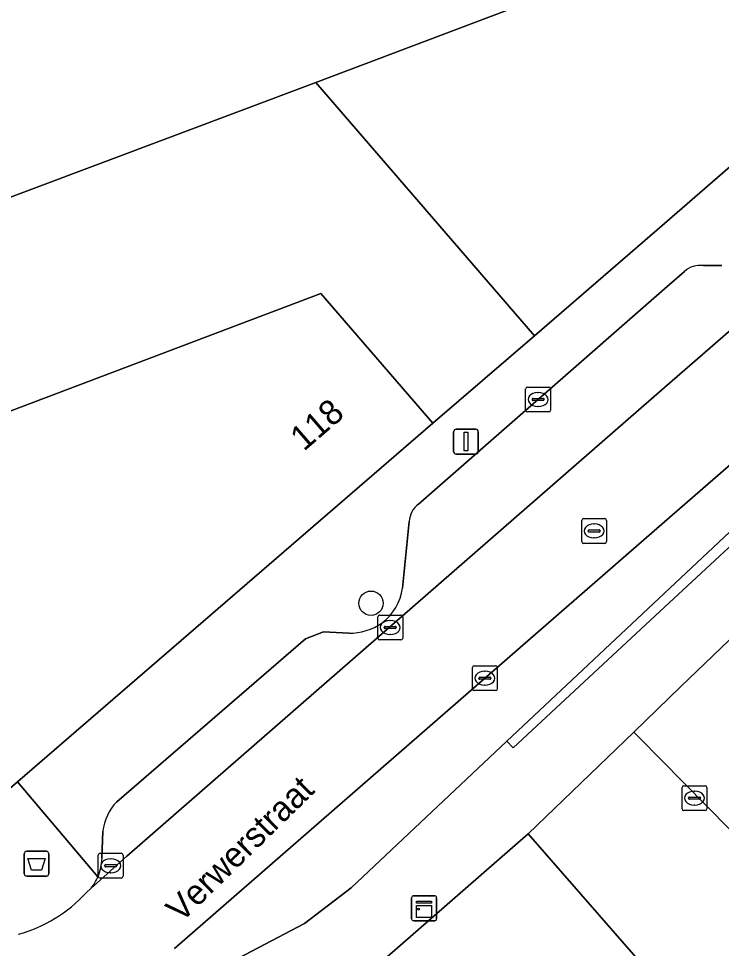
# Model space of a CAD drawing. Extents: x 160856 to 161310, y 384024 to 384878.
# Drawn here: x 160974.04 to 161002.28, y 384577.71 to 384615.1 of the extents above; entities that cross this region are included whole.
import ezdxf

# ---------------------------------------------------------------- set-up
doc = ezdxf.new("R2010")
doc.units = 0
for name, color, linetype in [('IMGEO_Afvalbak', 7, 'Continuous'), ('IMGEO_Boom', 7, 'Continuous'), ('IMGEO_Kast', 7, 'Continuous'), ('IMGEO_Kolk', 7, 'Continuous'), ('IMGEO_Lichtmast', 7, 'Continuous'), ('IMGEO_Openbare_ruimte_label', 7, 'Continuous'), ('IMGEO_Pand', 7, 'Continuous'), ('IMGEO_Pand_nummerreeks', 7, 'Continuous'), ('IMGEO_Parkeervlak_open', 7, 'Continuous'), ('IMGEO_Rijbaan_lokaal_gesloten', 7, 'Continuous'), ('IMGEO_Rijbaan_lokaal_open', 7, 'Continuous'), ('IMGEO_Rioolput', 7, 'Continuous'), ('IMGEO_Voetpad_open', 7, 'Continuous')]:
    doc.layers.add(name, color=color, linetype=linetype)

msp = doc.modelspace()

# ---------------------------------------------------------------- linework, layer by layer
at = {"layer": 'IMGEO_Afvalbak'}
for p, q in [((160974.362, 384581.619), (160975.152, 384581.619)), ((160975.152, 384581.619), (160974.362, 384581.619)), ((160974.262, 384580.719), (160974.262, 384581.519)), ((160974.262, 384581.519), (160974.262, 384580.719)), ((160975.252, 384581.519), (160975.252, 384580.719)), ((160975.252, 384580.719), (160975.252, 384581.519)), ((160975.152, 384580.619), (160974.362, 384580.619)), ((160974.362, 384580.619), (160975.152, 384580.619))]:
    msp.add_line(p, q, dxfattribs=at)
msp.add_lwpolyline([(160974.405, 384581.333), (160975.109, 384581.333), (160974.96, 384580.863), (160974.554, 384580.863), (160974.405, 384581.333)], dxfattribs=at)
for centre, start, end in [((160974.362, 384581.519), 90, 180), ((160974.362, 384581.519), 90, 180), ((160975.152, 384581.519), 0, 90), ((160975.152, 384581.519), 360, 90), ((160974.362, 384580.719), 180, 270), ((160974.362, 384580.719), 180, 270), ((160975.152, 384580.719), 270, 0), ((160975.152, 384580.719), 270, 0)]:
    msp.add_arc(centre, 0.1, start, end, dxfattribs=at)
at = {"layer": 'IMGEO_Boom'}
msp.add_circle((160988.2, 384591.593), 0.489, dxfattribs=at)
at = {"layer": 'IMGEO_Kast'}
for p, q in [((160989.833, 384578.904), (160989.833, 384579.745)), ((160989.833, 384579.745), (160989.833, 384578.904)), ((160989.908, 384579.829), (160990.749, 384579.829)), ((160990.749, 384579.829), (160989.908, 384579.829)), ((160990.833, 384579.754), (160990.833, 384578.913)), ((160990.833, 384578.913), (160990.833, 384579.754)), ((160990.758, 384578.829), (160989.917, 384578.829)), ((160989.917, 384578.829), (160990.758, 384578.829))]:
    msp.add_line(p, q, dxfattribs=at)
for points in [[(160990.028, 384579.619), (160990.628, 384579.619), (160990.628, 384579.534), (160990.028, 384579.534), (160990.028, 384579.619)], [(160990.028, 384579.444), (160990.628, 384579.444), (160990.628, 384578.955), (160990.028, 384578.955), (160990.028, 384579.444)]]:
    msp.add_lwpolyline(points, dxfattribs=at)
msp.add_circle((160990.112, 384579.293), 0.0377, dxfattribs=at)
for centre, start, end in [((160989.911, 384579.751), 92.4484, 184.2845), ((160989.911, 384579.751), 92.4484, 184.2845), ((160990.755, 384579.751), 2.4484, 94.2845), ((160990.755, 384579.751), 2.4484, 94.2845), ((160989.911, 384578.907), 182.4484, 274.2845), ((160989.911, 384578.907), 182.4484, 274.2845), ((160990.755, 384578.907), 272.4484, 4.2845), ((160990.755, 384578.907), 272.4484, 4.2845)]:
    msp.add_arc(centre, 0.0779, start, end, dxfattribs=at)
at = {"layer": 'IMGEO_Kolk'}
for p, q in [((160994.49, 384600.285), (160995.342, 384600.285)), ((160994.415, 384599.359), (160994.415, 384600.211)), ((160994.903, 384600.065), (160994.928, 384600.065)), ((160995.416, 384600.211), (160995.416, 384599.359)), ((160994.674, 384599.779), (160994.674, 384599.791)), ((160995.112, 384599.742), (160994.714, 384599.742)), ((160994.717, 384599.828), (160995.115, 384599.828)), ((160994.926, 384599.505), (160994.901, 384599.505)), ((160995.158, 384599.791), (160995.158, 384599.779)), ((160995.342, 384599.285), (160994.49, 384599.285)), ((160988.472, 384590.192), (160988.472, 384591.044)), ((160988.547, 384591.118), (160989.399, 384591.118)), ((160988.96, 384590.898), (160988.985, 384590.898)), ((160989.473, 384591.044), (160989.473, 384590.192)), ((160988.731, 384590.612), (160988.731, 384590.624)), ((160989.169, 384590.575), (160988.771, 384590.575)), ((160988.774, 384590.661), (160989.172, 384590.661)), ((160989.215, 384590.624), (160989.215, 384590.612)), ((160988.983, 384590.338), (160988.958, 384590.338)), ((160989.399, 384590.118), (160988.547, 384590.118)), ((160992.35, 384589.079), (160993.202, 384589.079)), ((160992.275, 384588.153), (160992.275, 384589.005)), ((160992.763, 384588.859), (160992.788, 384588.859)), ((160993.276, 384589.005), (160993.276, 384588.153)), ((160992.534, 384588.573), (160992.534, 384588.585)), ((160992.972, 384588.536), (160992.574, 384588.536)), ((160992.577, 384588.622), (160992.975, 384588.622)), ((160992.786, 384588.299), (160992.761, 384588.299)), ((160993.018, 384588.585), (160993.018, 384588.573)), ((160993.202, 384588.079), (160992.35, 384588.079)), ((161000.701, 384583.33), (161000.701, 384584.182)), ((161000.776, 384584.256), (161001.628, 384584.256)), ((161001.702, 384584.182), (161001.702, 384583.33)), ((161001.003, 384583.799), (161001.401, 384583.799)), ((161001.189, 384584.036), (161001.214, 384584.036)), ((161000.96, 384583.75), (161000.96, 384583.762)), ((161001.398, 384583.713), (161001, 384583.713)), ((161001.212, 384583.476), (161001.187, 384583.476)), ((161001.444, 384583.762), (161001.444, 384583.75)), ((161001.628, 384583.256), (161000.776, 384583.256)), ((160977.236, 384580.612), (160977.236, 384581.464)), ((160977.311, 384581.538), (160978.163, 384581.538)), ((160977.724, 384581.318), (160977.749, 384581.318)), ((160978.237, 384581.464), (160978.237, 384580.612)), ((160977.495, 384581.032), (160977.495, 384581.044)), ((160977.933, 384580.995), (160977.535, 384580.995)), ((160977.538, 384581.081), (160977.936, 384581.081)), ((160977.979, 384581.044), (160977.979, 384581.032)), ((160978.163, 384580.538), (160977.311, 384580.538)), ((160977.747, 384580.758), (160977.722, 384580.758))]:
    msp.add_line(p, q, dxfattribs=at)
for points in [[(160994.49, 384600.285), (160995.342, 384600.285)], [(160994.415, 384599.359), (160994.415, 384600.211)], [(160995.416, 384600.211), (160995.416, 384599.359)], [(160995.342, 384599.285), (160994.49, 384599.285)], [(160988.472, 384590.192), (160988.472, 384591.044)], [(160988.547, 384591.118), (160989.399, 384591.118)], [(160989.473, 384591.044), (160989.473, 384590.192)], [(160989.399, 384590.118), (160988.547, 384590.118)], [(160992.35, 384589.079), (160993.202, 384589.079)], [(160992.275, 384588.153), (160992.275, 384589.005)], [(160993.276, 384589.005), (160993.276, 384588.153)], [(160993.202, 384588.079), (160992.35, 384588.079)], [(161000.701, 384583.33), (161000.701, 384584.182)], [(161000.776, 384584.256), (161001.628, 384584.256)], [(161001.702, 384584.182), (161001.702, 384583.33)], [(161001.628, 384583.256), (161000.776, 384583.256)], [(160977.236, 384580.612), (160977.236, 384581.464)], [(160977.311, 384581.538), (160978.163, 384581.538)], [(160978.237, 384581.464), (160978.237, 384580.612)], [(160978.163, 384580.538), (160977.311, 384580.538)]]:
    msp.add_lwpolyline(points, dxfattribs=at)
for centre, radius, start, end in [((160994.492, 384600.209), 0.0765, 91.552, 178.448), ((160994.492, 384600.209), 0.0765, 91.552, 178.448), ((160995.34, 384600.209), 0.0765, 1.552, 88.448), ((160995.34, 384600.209), 0.0765, 1.552, 88.448), ((160994.714, 384599.788), 0.0403, 85.8775, 175.7526), ((160994.711, 384599.778), 0.0366, 178.938, 274.7102), ((160995.115, 384599.785), 0.043, 264.8664, 352.4533), ((160995.119, 384599.79), 0.0386, 1.7309, 96.639), ((160994.492, 384599.361), 0.0765, 181.552, 268.448), ((160994.492, 384599.361), 0.0765, 181.552, 268.448), ((160995.34, 384599.361), 0.0765, 271.552, 358.448), ((160995.34, 384599.361), 0.0765, 271.552, 358.448), ((160988.549, 384591.042), 0.0765, 91.552, 178.448), ((160988.549, 384591.042), 0.0765, 91.552, 178.448), ((160989.397, 384591.042), 0.0765, 1.552, 88.448), ((160989.397, 384591.042), 0.0765, 1.552, 88.448), ((160988.771, 384590.621), 0.0403, 85.8775, 175.7526), ((160988.768, 384590.611), 0.0366, 178.938, 274.7102), ((160989.172, 384590.618), 0.043, 264.8664, 352.4533), ((160989.176, 384590.623), 0.0386, 1.7309, 96.639), ((160988.549, 384590.194), 0.0765, 181.552, 268.448), ((160988.549, 384590.194), 0.0765, 181.552, 268.448), ((160989.397, 384590.194), 0.0765, 271.552, 358.448), ((160989.397, 384590.194), 0.0765, 271.552, 358.448), ((160992.352, 384589.003), 0.0765, 91.552, 178.448), ((160992.352, 384589.003), 0.0765, 91.552, 178.448), ((160993.2, 384589.003), 0.0765, 1.552, 88.448), ((160993.2, 384589.003), 0.0765, 1.552, 88.448), ((160992.574, 384588.582), 0.0403, 85.8775, 175.7526), ((160992.571, 384588.572), 0.0366, 178.938, 274.7102), ((160992.975, 384588.579), 0.043, 264.8664, 352.4533), ((160992.979, 384588.584), 0.0386, 1.7309, 96.639), ((160992.352, 384588.155), 0.0765, 181.552, 268.448), ((160992.352, 384588.155), 0.0765, 181.552, 268.448), ((160993.2, 384588.155), 0.0765, 271.552, 358.448), ((160993.2, 384588.155), 0.0765, 271.552, 358.448), ((161000.778, 384584.18), 0.0765, 91.552, 178.448), ((161000.778, 384584.18), 0.0765, 91.552, 178.448), ((161001.626, 384584.18), 0.0765, 1.552, 88.448), ((161001.626, 384584.18), 0.0765, 1.552, 88.448), ((161001, 384583.759), 0.0403, 85.8775, 175.7526), ((161001.405, 384583.761), 0.0386, 1.7309, 96.639), ((161000.997, 384583.749), 0.0366, 178.938, 274.7102), ((161001.401, 384583.756), 0.043, 264.8664, 352.4533), ((161000.778, 384583.332), 0.0765, 181.552, 268.448), ((161000.778, 384583.332), 0.0765, 181.552, 268.448), ((161001.626, 384583.332), 0.0765, 271.552, 358.448), ((161001.626, 384583.332), 0.0765, 271.552, 358.448), ((160977.313, 384581.462), 0.0765, 91.552, 178.448), ((160977.313, 384581.462), 0.0765, 91.552, 178.448), ((160978.161, 384581.462), 0.0765, 1.552, 88.448), ((160978.161, 384581.462), 0.0765, 1.552, 88.448), ((160977.535, 384581.041), 0.0403, 85.8775, 175.7526), ((160977.532, 384581.031), 0.0366, 178.938, 274.7102), ((160977.936, 384581.038), 0.043, 264.8664, 352.4533), ((160977.94, 384581.043), 0.0386, 1.7309, 96.639), ((160977.313, 384580.614), 0.0765, 181.552, 268.448), ((160977.313, 384580.614), 0.0765, 181.552, 268.448), ((160978.161, 384580.614), 0.0765, 271.552, 358.448), ((160978.161, 384580.614), 0.0765, 271.552, 358.448)]:
    msp.add_arc(centre, radius, start, end, dxfattribs=at)
for centre, major_axis, ratio, start_param, end_param in [((160994.902, 384599.785), (-0.387, 0.002), 0.722429, 4.712389, 7.853982), ((160994.927, 384599.785), (-0.39, 0.002), 0.717154, 1.570796, 4.712389), ((160988.959, 384590.618), (-0.387, 0.002), 0.722429, 4.712389, 7.853982), ((160988.984, 384590.618), (-0.39, 0.002), 0.717154, 1.570796, 4.712389), ((160992.762, 384588.579), (-0.387, 0.002), 0.722429, 4.712389, 7.853982), ((160992.787, 384588.579), (-0.39, 0.002), 0.717154, 1.570796, 4.712389), ((161001.188, 384583.756), (-0.387, 0.002), 0.722429, 4.712389, 7.853982), ((161001.213, 384583.756), (-0.39, 0.002), 0.717154, 1.570796, 4.712389), ((160977.723, 384581.038), (-0.387, 0.002), 0.722429, 4.712389, 7.853982), ((160977.748, 384581.038), (-0.39, 0.002), 0.717154, 1.570796, 4.712389)]:
    msp.add_ellipse(centre, major_axis=major_axis, ratio=ratio, start_param=start_param, end_param=end_param, dxfattribs=at)
at = {"layer": 'IMGEO_Lichtmast'}
for p, q in [((160991.519, 384597.69), (160991.519, 384598.49)), ((160991.519, 384598.49), (160991.519, 384597.69)), ((160991.619, 384598.59), (160992.409, 384598.59)), ((160992.409, 384598.59), (160991.619, 384598.59)), ((160992.509, 384598.49), (160992.509, 384597.69)), ((160992.509, 384597.69), (160992.509, 384598.49)), ((160992.409, 384597.59), (160991.619, 384597.59)), ((160991.619, 384597.59), (160992.409, 384597.59))]:
    msp.add_line(p, q, dxfattribs=at)
msp.add_lwpolyline([(160991.939, 384598.465), (160992.089, 384598.465), (160992.089, 384597.715), (160991.939, 384597.715), (160991.939, 384598.465)], dxfattribs=at)
for centre, start, end in [((160991.619, 384598.49), 90, 180), ((160991.619, 384598.49), 90, 180), ((160992.409, 384598.49), 0, 90), ((160992.409, 384598.49), 360, 90), ((160991.619, 384597.69), 180, 270), ((160991.619, 384597.69), 180, 270), ((160992.409, 384597.69), 270, 0), ((160992.409, 384597.69), 270, 0)]:
    msp.add_arc(centre, 0.1, start, end, dxfattribs=at)
at = {"layer": 'IMGEO_Pand'}
for points in [[(160957.323, 384601.772), (160985.981, 384612.527), (161000, 384617.833), (161002.264, 384618.717), (161000, 384624.44), (160998.052, 384629.357), (160983.529, 384628.84), (160983.224, 384628.829), (160951.057, 384618.029), (160951.527, 384616.811)], [(161017.955, 384622.48), (161016.56, 384624.082), (161002.264, 384618.717), (161000, 384617.833), (160985.981, 384612.527), (160994.768, 384602.349), (161000, 384606.866)], [(160957.323, 384601.772), (160960.23, 384594.229), (160986.187, 384604.043), (160990.689, 384598.828), (160994.768, 384602.349), (160985.981, 384612.527)], [(160990.689, 384598.828), (160986.187, 384604.043), (160960.23, 384594.229), (160970.483, 384581.386), (160973.995, 384584.418)], [(160985.147, 384563.476), (161000.133, 384575.891), (160994.515, 384582.326), (160982.962, 384572.239), (160982.264, 384571.633), (160981.931, 384567.366), (160983.078, 384565.978)]]:
    msp.add_lwpolyline(points, close=True, dxfattribs=at)
at = {"layer": 'IMGEO_Parkeervlak_open'}
for points in [[(161038.406, 384628.276), (161000, 384594.865), (160980.308, 384577.714)], [(160976.957, 384580.135), (160977.321, 384580.465), (160978.384, 384581.429), (161000, 384600.273), (161021.935, 384619.355)], [(161002.299, 384605.176), (161001.56, 384605.167)], [(161000.794, 384604.925), (161000, 384604.231), (160990.109, 384595.581)], [(160979.156, 384575.363), (160985.52, 384578.721), (160987.397, 384580.151), (160993.662, 384586.043), (161003.916, 384595.689)], [(160989.729, 384594.881), (160989.47, 384592.198)], [(160987.307, 384590.386), (160986.284, 384590.445), (160985.567, 384590.158), (160977.982, 384583.606)], [(160977.426, 384582.422), (160977.387, 384581.339)]]:
    msp.add_lwpolyline(points, dxfattribs=at)
msp.add_lwpolyline([(160998.757, 384586.414), (160994.515, 384582.326), (161000.133, 384575.891), (161004.057, 384571.396), (161008.762, 384575.304), (161015.582, 384568.028), (161016.273, 384568.639), (160998.962, 384586.206)], close=True, dxfattribs=at)
for centre, radius, start, end in [((161001.414, 384604.295), 0.884, 80.5239, 134.5415), ((160990.711, 384594.801), 0.985, 127.6506, 175.3581), ((160987.302, 384592.534), 2.194, 307.7789, 351.1898), ((160987.298, 384592.787), 2.401, 270.2103, 304.1515), ((160979.406, 384582.215), 1.991, 135.6677, 174.0233), ((160975.308, 384581.411), 2.081, 336.6607, 358.0076), ((160975.215, 384581.442), 2.178, 323.1147, 336.8781)]:
    msp.add_arc(centre, radius, start, end, dxfattribs=at)
at = {"layer": 'IMGEO_Rijbaan_lokaal_gesloten'}
for points in [[(161045.97, 384635.823), (161048.906, 384638.739), (161096.984, 384685.767), (161094.179, 384688.665), (161093.847, 384688.359), (161047.62, 384642.996), (161045.943, 384641.353), (161041.622, 384637.072), (161035.757, 384631.338), (161021.935, 384619.355), (161000, 384600.273), (160978.384, 384581.429), (160977.321, 384580.465), (160976.957, 384580.135), (160976.745, 384579.943)], [(160980.308, 384577.714), (161000, 384594.865), (161038.406, 384628.276), (161045.97, 384635.823)]]:
    msp.add_lwpolyline(points, dxfattribs=at)
msp.add_arc((160972.41, 384583.977), 5.922, 285.9389, 317.0588, dxfattribs=at)
at = {"layer": 'IMGEO_Rijbaan_lokaal_open'}
msp.add_lwpolyline([(161003.233, 384590.726), (161000.653, 384588.241), (160998.757, 384586.414), (160998.962, 384586.206), (161016.273, 384568.639), (161020.812, 384572.002), (161005.851, 384587.997)], close=True, dxfattribs=at)
at = {"layer": 'IMGEO_Rioolput'}
for p, q in [((160996.667, 384594.074), (160996.667, 384594.926)), ((160996.742, 384595), (160997.594, 384595)), ((160997.155, 384594.78), (160997.18, 384594.78)), ((160997.668, 384594.926), (160997.668, 384594.074)), ((160996.926, 384594.494), (160996.926, 384594.506)), ((160997.364, 384594.457), (160996.966, 384594.457)), ((160996.969, 384594.543), (160997.367, 384594.543)), ((160997.41, 384594.506), (160997.41, 384594.494)), ((160997.594, 384594), (160996.742, 384594)), ((160997.178, 384594.22), (160997.153, 384594.22))]:
    msp.add_line(p, q, dxfattribs=at)
for points in [[(160996.667, 384594.074), (160996.667, 384594.926)], [(160996.742, 384595), (160997.594, 384595)], [(160997.668, 384594.926), (160997.668, 384594.074)], [(160997.594, 384594), (160996.742, 384594)]]:
    msp.add_lwpolyline(points, dxfattribs=at)
for centre, radius, start, end in [((160996.744, 384594.924), 0.0765, 91.552, 178.448), ((160996.744, 384594.924), 0.0765, 91.552, 178.448), ((160997.592, 384594.924), 0.0765, 1.552, 88.448), ((160997.592, 384594.924), 0.0765, 1.552, 88.448), ((160996.966, 384594.503), 0.0403, 85.8775, 175.7526), ((160996.963, 384594.493), 0.0366, 178.938, 274.7102), ((160997.367, 384594.5), 0.043, 264.8664, 352.4533), ((160997.371, 384594.505), 0.0386, 1.7309, 96.639), ((160996.744, 384594.076), 0.0765, 181.552, 268.448), ((160996.744, 384594.076), 0.0765, 181.552, 268.448), ((160997.592, 384594.076), 0.0765, 271.552, 358.448), ((160997.592, 384594.076), 0.0765, 271.552, 358.448)]:
    msp.add_arc(centre, radius, start, end, dxfattribs=at)
for centre, major_axis, ratio, start_param, end_param in [((160997.154, 384594.5), (-0.387, 0.002), 0.722429, 4.712389, 7.853982), ((160997.179, 384594.5), (-0.39, 0.002), 0.717154, 1.570796, 4.712389)]:
    msp.add_ellipse(centre, major_axis=major_axis, ratio=ratio, start_param=start_param, end_param=end_param, dxfattribs=at)
at = {"layer": 'IMGEO_Voetpad_open'}
for points in [[(160977.218, 384580.587), (160973.995, 384584.418), (160970.483, 384581.386), (160960.23, 384594.229), (160957.323, 384601.772), (160951.527, 384616.811), (160951.057, 384618.029), (160949.182, 384622.895), (160948.94, 384623.522), (160944.938, 384633.907), (160944.571, 384634.966), (160940.157, 384646.186), (160937.67, 384652.508), (160937.451, 384653.082), (160937.202, 384653.736), (160935.494, 384658.22), (160935.209, 384658.967), (160933.47, 384663.572), (160929.276, 384674.544)], [(161043.184, 384645.796), (161041.458, 384644.107), (161037.434, 384640.168), (161033.664, 384636.809), (161027.384, 384631.214), (161017.955, 384622.48), (161000, 384606.866), (160994.768, 384602.349), (160990.689, 384598.828), (160973.995, 384584.418), (160977.218, 384580.587)], [(160982.962, 384572.239), (160994.515, 384582.326), (160998.757, 384586.414), (161000.653, 384588.241), (161003.233, 384590.726), (161003.448, 384590.933), (161003.819, 384591.291), (161008.133, 384595.448), (161012.864, 384599.573), (161025.93, 384610.963)], [(161001.56, 384605.167), (161002.299, 384605.176)], [(160990.109, 384595.581), (161000, 384604.231), (161000.794, 384604.925)], [(161004.223, 384595.359), (161000, 384591.435), (160993.911, 384585.775), (160993.662, 384586.043), (160987.397, 384580.151), (160985.52, 384578.721), (160979.156, 384575.363)], [(160989.47, 384592.198), (160989.729, 384594.881)], [(160977.982, 384583.606), (160985.567, 384590.158), (160986.284, 384590.445), (160987.307, 384590.386)], [(160977.387, 384581.339), (160977.426, 384582.422)], [(160976.745, 384579.943), (160976.957, 384580.135)]]:
    msp.add_lwpolyline(points, dxfattribs=at)
msp.add_lwpolyline([(161000, 384591.435), (161004.223, 384595.359), (161003.916, 384595.689), (160993.662, 384586.043), (160993.911, 384585.775)], close=True, dxfattribs=at)
for centre, radius, start, end in [((161001.414, 384604.295), 0.884, 80.5239, 134.5415), ((160990.711, 384594.801), 0.985, 127.6506, 175.3581), ((160987.302, 384592.534), 2.194, 307.7789, 351.1898), ((160987.298, 384592.787), 2.401, 270.2103, 304.1515), ((160979.406, 384582.215), 1.991, 135.6677, 174.0233), ((160975.308, 384581.411), 2.081, 336.6607, 358.0076), ((160975.215, 384581.442), 2.178, 323.1147, 336.8781), ((160972.41, 384583.977), 5.922, 285.9389, 317.0588)]:
    msp.add_arc(centre, radius, start, end, dxfattribs=at)

# ---------------------------------------------------------------- texts
at = {"layer": 'IMGEO_Openbare_ruimte_label'}
msp.add_text('Verwerstraat', height=1, rotation=44.4327, dxfattribs=at).set_placement((160980.566, 384578.712))
at = {"layer": 'IMGEO_Pand_nummerreeks'}
msp.add_text('118', height=1, rotation=40.8018, dxfattribs=at).set_placement((160985.499, 384597.678))

doc.saveas('drawing.dxf')
